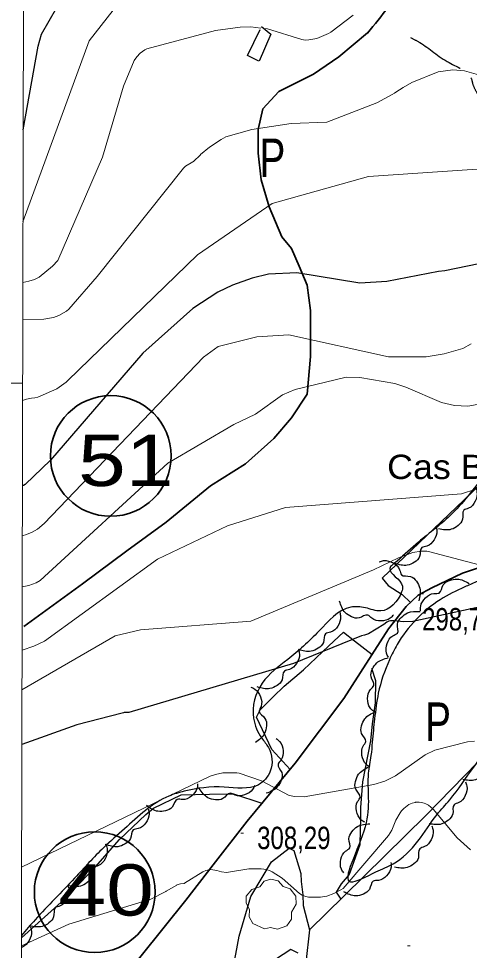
# Model space of a CAD drawing. Extents: x 483847 to 488453, y 4383581 to 4386795.
# Drawn here: x 484103 to 484278.8, y 4385778.6 to 4386142.3 of the extents above; entities that cross this region are included whole.
import ezdxf
from ezdxf.enums import TextEntityAlignment as Align

# ---------------------------------------------------------------- set-up
doc = ezdxf.new("R2010")
doc.units = 0
doc.header["$LTSCALE"] = 3.8
doc.linetypes.add('LONG_DASHED', pattern=[7.5, 6, -1.5])
doc.linetypes.add('MEDIUM_DASHED', pattern=[4.5, 3, -1.5])
for name, color, linetype, lineweight in [('1', 7, 'Continuous', 13), ('13', 7, 'Continuous', 25), ('25', 7, 'LONG_DASHED', 25), ('27', 7, 'Continuous', 25), ('29', 7, 'Continuous', 13), ('38', 7, 'Continuous', 25), ('48', 7, 'MEDIUM_DASHED', 25), ('51', 7, 'Continuous', 13), ('6', 7, 'Continuous', 35), ('7', 7, 'Continuous', 13), ('8', 7, 'Continuous', 25), ('9', 7, 'Continuous', 13)]:
    doc.layers.add(name, color=color, linetype=linetype, lineweight=lineweight)
doc.layers.add('31', color=7, linetype='Continuous')
doc.layers.add('5', color=7, linetype='Continuous')

msp = doc.modelspace()

# ---------------------------------------------------------------- linework, layer by layer
at = {"layer": '1'}
msp.add_line((484104.53, 4386000), (484034.04, 4386000), dxfattribs=at)
msp.add_lwpolyline([(484105.5, 4386448.1), (487681.9, 4386441.2), (487678, 4384129), (484100.5, 4384135.8)], close=True, dxfattribs=at)
at = {"layer": '25'}
for points in [[(484244.76, 4385923.91), (484247.1, 4385921.01), (484252.56, 4385917.53), (484255.79, 4385914.34)], [(484208.88, 4385849.22), (484201.8, 4385856.99), (484195.77, 4385869.63), (484197.2, 4385872.41), (484202.26, 4385877.53), (484206.58, 4385881.72), (484214.07, 4385888.1), (484223.96, 4385897.44), (484229.65, 4385902.75), (484233.96, 4385899.46), (484240.84, 4385894.12)], [(484240.66, 4385888.73), (484242.2, 4385883.98), (484242.03, 4385875.17), (484240.87, 4385866.96), (484240.25, 4385860.34), (484237.08, 4385844.39), (484236.29, 4385834.37), (484236.38, 4385830.12), (484236.25, 4385825.6), (484236.08, 4385819.73), (484231.97, 4385808.21), (484228.85, 4385804.57), (484226.84, 4385801.28), (484228.69, 4385798.57)], [(484104.06, 4385783.51), (484120.82, 4385798.56), (484133.03, 4385811.23), (484142.38, 4385821.8), (484152.55, 4385831.63), (484155.54, 4385834.01), (484166.35, 4385839.3), (484177.48, 4385839.5), (484186.74, 4385839.65), (484197.91, 4385835.98)], [(484186.67, 4385771.46), (484189.03, 4385784.05), (484193.62, 4385799.65), (484198.03, 4385807.02), (484201.67, 4385813.17), (484208.56, 4385818.42), (484210.32, 4385817.49), (484213.12, 4385808.58), (484213.24, 4385805.49), (484213.9, 4385800.29), (484213.92, 4385796.06), (484216.49, 4385786.52), (484214.96, 4385773.81)], [(484212.04, 4385777.4), (484209.19, 4385778.88), (484200.23, 4385773.07)]]:
    msp.add_lwpolyline(points, dxfattribs=at)
at = {"layer": '27'}
for points in [[(484521.83, 4386129.21), (484508.32, 4386113.74), (484496.36, 4386106.72), (484484.98, 4386099.78), (484479.47, 4386096.2), (484474.08, 4386092.03), (484465.73, 4386080.11), (484463.37, 4386070.85), (484462.34, 4386064.2), (484460.12, 4386059.8), (484454.25, 4386057.63), (484450.41, 4386060.19), (484441.8, 4386070.58), (484436.87, 4386074.16), (484423.6, 4386076.36), (484410.55, 4386071.73), (484408.24, 4386063.13), (484410.15, 4386056.7), (484413.78, 4386045.09), (484413.88, 4386035.22), (484411.69, 4386031.3), (484398.49, 4386024.75), (484365.27, 4386031.06), (484366.6, 4386045.65), (484370.89, 4386062.61), (484370.84, 4386067.52), (484358.49, 4386079.04), (484346.94, 4386070.29), (484334.44, 4386055.37), (484325.94, 4386044.05), (484321.89, 4386034.49), (484320.96, 4386033.92), (484314.12, 4386023.53), (484311.47, 4386011.99), (484311.33, 4386008.15), (484312.05, 4385996.07), (484306.71, 4385986.89), (484300.7, 4385979.39), (484285.98, 4385965.15), (484272.14, 4385949.06), (484258.95, 4385937.98), (484250.68, 4385930.52)], [(484281.23, 4385959.28), (484281.77, 4385957.59), (484281.06, 4385953.87), (484278.52, 4385951.18), (484276.64, 4385950.37), (484276.14, 4385946.85), (484274.39, 4385944.43), (484271.76, 4385942.94), (484266.8, 4385943.07)], [(484265.78, 4385944.14), (484266.14, 4385942.4), (484265.02, 4385938.78), (484262.2, 4385936.39), (484260.24, 4385935.79), (484259.36, 4385932.35), (484257.36, 4385930.13), (484254.58, 4385928.95), (484249.66, 4385929.62)], [(484310.59, 4385907.93), (484296.14, 4385903.44), (484289.2, 4385891.6), (484294.68, 4385878.62), (484298.16, 4385870.38), (484294.8, 4385866.22), (484280.49, 4385850.12), (484271.14, 4385837.28), (484266.23, 4385831.62), (484258.71, 4385821.16), (484249.08, 4385812.33), (484242.34, 4385809.17), (484232.5, 4385805.26), (484238.16, 4385826.81), (484239.38, 4385847.7), (484240.42, 4385854.63), (484240.92, 4385859.9), (484241.84, 4385868.97), (484243.29, 4385878.92), (484247.62, 4385892), (484250.65, 4385897.95), (484267.41, 4385915.44), (484276.98, 4385920.43), (484281.49, 4385922.38), (484297.68, 4385928.57), (484310.92, 4385937.54), (484321.22, 4385936.51), (484326.98, 4385931.86), (484335.65, 4385926.29), (484346.17, 4385923.11), (484355.76, 4385923.88), (484349.64, 4385914.35), (484340.44, 4385905.87), (484332.13, 4385896.62), (484324.31, 4385893.84), (484320.63, 4385896.21), (484315.57, 4385899.62), (484312.38, 4385905.09), (484310.59, 4385907.93)], [(484243.66, 4385930.28), (484245.37, 4385930.73), (484249.06, 4385929.82), (484251.6, 4385927.15), (484252.32, 4385925.22), (484255.81, 4385924.54), (484258.13, 4385922.67), (484259.48, 4385919.96), (484259.09, 4385915.02)], [(484250.68, 4385930.52), (484247.76, 4385927.65), (484252.69, 4385920.71), (484252.36, 4385918.5), (484244.24, 4385911.06), (484238.24, 4385912.3), (484232.52, 4385912.53), (484220.11, 4385903.19), (484207.93, 4385892.15), (484198.02, 4385882.9), (484194.6, 4385869.16), (484197.83, 4385861.42), (484200.41, 4385857.74), (484201.16, 4385848.51), (484196.55, 4385843.23), (484183.21, 4385842.3), (484167.6, 4385840.69), (484161.59, 4385838.79), (484144.28, 4385826.05), (484136.18, 4385818.7), (484124.8, 4385806.73), (484109.41, 4385790.47), (484104.06, 4385784.41)], [(484259.8, 4385911.13), (484259.82, 4385912.9), (484261.71, 4385916.2), (484264.97, 4385917.92), (484267.02, 4385918.08), (484268.62, 4385921.25), (484271.06, 4385922.98), (484274.03, 4385923.53), (484278.68, 4385921.81)], [(484249.17, 4385909.48), (484247.92, 4385908.22), (484244.28, 4385907.16), (484240.73, 4385908.19), (484239.15, 4385909.49), (484235.79, 4385908.33), (484232.84, 4385908.78), (484230.32, 4385910.44), (484228.16, 4385914.91)], [(484228.23, 4385910.56), (484228.59, 4385908.82), (484227.48, 4385905.19), (484224.68, 4385902.8), (484222.71, 4385902.19), (484221.85, 4385898.74), (484219.85, 4385896.52), (484217.07, 4385895.33), (484212.15, 4385895.98)], [(484247.2, 4385893), (484246.46, 4385894.61), (484246.73, 4385898.39), (484248.93, 4385901.36), (484250.71, 4385902.39), (484250.78, 4385905.94), (484252.23, 4385908.55), (484254.67, 4385910.34), (484259.61, 4385910.8)], [(484103.97, 4385586.23), (484176.02, 4385651.64), (484253.85, 4385717.49), (484302.32, 4385770.44), (484308.55, 4385772.67), (484311.22, 4385771.78), (484341.46, 4385750.86), (484349.91, 4385746.42), (484353.91, 4385745.08), (484362.36, 4385744.64), (484369.92, 4385748.2), (484474.44, 4385847.42), (484504.68, 4385882.13), (484503.35, 4385888.8), (484498.9, 4385892.81), (484494.45, 4385895.92), (484482, 4385891.47), (484439.31, 4385856.77), (484421.52, 4385849.65), (484402.84, 4385853.65), (484394.83, 4385855.43), (484392.16, 4385853.65), (484393.94, 4385847.42)], [(484212.15, 4385895.98), (484212.52, 4385894.24), (484211.41, 4385890.62), (484208.6, 4385888.22), (484206.64, 4385887.61), (484205.77, 4385884.17), (484203.77, 4385881.95), (484200.99, 4385880.75), (484196.08, 4385881.41)], [(484241.35, 4385871.93), (484240.11, 4385873.21), (484239.12, 4385876.87), (484240.21, 4385880.39), (484241.55, 4385881.95), (484240.44, 4385885.33), (484240.95, 4385888.27), (484242.66, 4385890.76), (484247.17, 4385892.83)], [(484193.51, 4385881.34), (484195.11, 4385880.58), (484197.34, 4385877.51), (484197.56, 4385873.82), (484196.86, 4385871.89), (484199.08, 4385869.12), (484199.64, 4385866.19), (484198.92, 4385863.25), (484195.43, 4385859.73)], [(484239.94, 4385850.17), (484238.51, 4385851.21), (484236.91, 4385854.65), (484237.38, 4385858.31), (484238.44, 4385860.08), (484236.77, 4385863.22), (484236.77, 4385866.2), (484238.03, 4385868.95), (484242.12, 4385871.76)], [(484203.46, 4385861.23), (484204.8, 4385860.07), (484206.13, 4385856.52), (484205.37, 4385852.91), (484204.18, 4385851.23), (484205.59, 4385847.97), (484205.36, 4385844.99), (484203.89, 4385842.35), (484199.59, 4385839.88)], [(484290.5, 4385861.54), (484291.06, 4385859.85), (484290.37, 4385856.12), (484287.85, 4385853.42), (484285.97, 4385852.6), (484285.5, 4385849.07), (484283.77, 4385846.64), (484281.15, 4385845.14), (484276.19, 4385845.23)], [(484237.99, 4385828.57), (484236.53, 4385829.58), (484234.83, 4385832.97), (484235.21, 4385836.64), (484236.21, 4385838.43), (484234.46, 4385841.53), (484234.38, 4385844.51), (484235.56, 4385847.29), (484239.57, 4385850.21)], [(484172.82, 4385843.6), (484172.6, 4385841.84), (484170.37, 4385838.78), (484166.93, 4385837.42), (484164.88, 4385837.49), (484162.93, 4385834.51), (484160.32, 4385833.07), (484157.31, 4385832.84), (484152.87, 4385835.07)], [(484277.26, 4385844.38), (484277.83, 4385842.7), (484277.17, 4385838.97), (484274.68, 4385836.24), (484272.81, 4385835.4), (484272.37, 4385831.87), (484270.66, 4385829.42), (484268.05, 4385827.9), (484263.09, 4385827.95)], [(484195.09, 4385842.96), (484194.27, 4385841.38), (484191.13, 4385839.27), (484187.43, 4385839.17), (484185.53, 4385839.94), (484182.68, 4385837.8), (484179.73, 4385837.34), (484176.82, 4385838.16), (484173.42, 4385841.76)], [(484153.6, 4385833.67), (484153.87, 4385831.92), (484152.58, 4385828.35), (484149.65, 4385826.1), (484147.66, 4385825.6), (484146.62, 4385822.2), (484144.51, 4385820.09), (484141.67, 4385819.04), (484136.8, 4385819.94)], [(484229.8, 4385808.79), (484228.87, 4385810.31), (484228.7, 4385814.1), (484230.53, 4385817.3), (484232.17, 4385818.53), (484231.83, 4385822.07), (484232.96, 4385824.83), (484235.17, 4385826.9), (484240.02, 4385827.94)], [(484264.1, 4385827.14), (484264.63, 4385825.45), (484263.89, 4385821.73), (484261.34, 4385819.06), (484259.45, 4385818.26), (484258.93, 4385814.74), (484257.17, 4385812.33), (484254.53, 4385810.86), (484249.57, 4385811.02)], [(484137.05, 4385819.64), (484137.54, 4385817.93), (484136.71, 4385814.23), (484134.09, 4385811.63), (484132.17, 4385810.88), (484131.57, 4385807.38), (484129.74, 4385805.02), (484127.06, 4385803.62), (484122.11, 4385803.91)], [(484248.22, 4385812.82), (484248.26, 4385811.05), (484246.52, 4385807.68), (484243.32, 4385805.83), (484241.29, 4385805.58), (484239.81, 4385802.35), (484237.45, 4385800.52), (484234.5, 4385799.84), (484229.78, 4385801.37)], [(484122.11, 4385803.9), (484122.61, 4385802.2), (484121.78, 4385798.5), (484119.16, 4385795.89), (484117.25, 4385795.14), (484116.65, 4385791.63), (484114.82, 4385789.27), (484112.15, 4385787.86), (484107.2, 4385788.14)], [(484107.55, 4385787.81), (484108.01, 4385786.1), (484107.11, 4385782.42), (484104.45, 4385779.86), (484104.05, 4385779.71)]]:
    msp.add_spline(points, degree=3, dxfattribs=at)
at = {"layer": '29'}
msp.add_lwpolyline([(484198.92, 4385786.93), (484194.38, 4385789.05), (484192.97, 4385791.59), (484193.07, 4385794.57), (484191.7, 4385796.98), (484191.74, 4385799.73), (484193.9, 4385802.33), (484197.09, 4385803.33), (484198.74, 4385805.52), (484201.31, 4385806.35), (484204.17, 4385805.7), (484206.12, 4385803.43), (484208.93, 4385802.61), (484211.06, 4385799.76), (484211.3, 4385796.63), (484209.42, 4385793.48), (484209.42, 4385790.8), (484207.6, 4385788.19), (484203.98, 4385786.85), (484201.21, 4385787.48)], close=True, dxfattribs=at)
at = {"layer": '38', "linetype": 'LONG_DASHED'}
msp.add_spline([(484255.9, 4386134.9), (484259.44, 4386133.02), (484270.89, 4386125.14), (484279.81, 4386118.06), (484279.96, 4386117.37), (484281.33, 4386114.11), (484286.93, 4386102.77), (484290.45, 4386094.05), (484338.18, 4386033.14), (484340.34, 4386027.35), (484343.3, 4386021.56), (484344.9, 4386017.72), (484345.67, 4386015.54)], degree=3, dxfattribs=at)
at = {"layer": '48'}
msp.add_lwpolyline([(484201.31, 4386136.21), (484196.74, 4386125.7), (484192.21, 4386127.89), (484197.76, 4386139.26)], close=True, dxfattribs=at)
at = {"layer": '51'}
for points in [[(484440.57, 4386075.07), (484408.1, 4386079.76), (484317.55, 4385993.99), (484276.69, 4385954.3), (484244.76, 4385923.91)], [(484317.36, 4385888.26), (484261.85, 4385831.27), (484229.89, 4385799.76), (484216.49, 4385786.52)]]:
    msp.add_lwpolyline(points, dxfattribs=at)
at = {"layer": '6'}
for points in [[(484239.1, 4386136.78), (484227.91, 4386127.44), (484218.03, 4386120.66), (484204.44, 4386113.88), (484198.27, 4386107.09), (484196.42, 4386099.08), (484196.42, 4386089.83), (484197.65, 4386079.35), (484200.74, 4386068.86), (484205.68, 4386057.15), (484209.36, 4386052.55)], [(484209.36, 4386052.55), (484212.47, 4386045.65), (484215.56, 4386038.25), (484216.8, 4386028.37), (484216.8, 4386018.5), (484216.8, 4386010.48), (484215.56, 4385995.67), (484209.38, 4385986.41), (484202.59, 4385978.39), (484191.47, 4385968.52), (484177.89, 4385959.88), (484160.6, 4385945.68), (484145.16, 4385934.58), (484127.86, 4385921.62), (484105.01, 4385904.96)], [(484103.92, 4385718.57), (484111.72, 4385728.95), (484132.39, 4385753.72), (484150.74, 4385776.42), (484168.25, 4385798.21), (484178.85, 4385811.99), (484192.12, 4385829), (484210.84, 4385851.58), (484229.9, 4385876.92), (484247.2, 4385904.12), (484254.19, 4385912.82), (484258.83, 4385917.22), (484264.2, 4385920.12), (484276.08, 4385925.76), (484289.25, 4385930.22), (484301.63, 4385935.61), (484316.4, 4385948.98), (484330.76, 4385961.22)]]:
    msp.add_lwpolyline(points, dxfattribs=at)
for centre in [(484138.92, 4385971.58), (484132.67, 4385801.3)]:
    msp.add_circle(centre, 23.55, dxfattribs=at)
msp.add_spline([(484576.61, 4386447.19), (484575.13, 4386446.53), (484575.18, 4386444.85), (484580.13, 4386440.31), (484591.1, 4386435.01), (484598.73, 4386428.86), (484602.1, 4386423.08), (484602.37, 4386415.22), (484599.42, 4386408.45), (484594.78, 4386406.63), (484585.36, 4386406.05), (484576.72, 4386406.48), (484563.21, 4386405.29), (484545.28, 4386400.82), (484534.96, 4386398.38), (484521.91, 4386395.52), (484514.17, 4386392.31), (484513.85, 4386387.73), (484523.95, 4386384.82), (484528.86, 4386384.69), (484538.58, 4386383.69), (484545.75, 4386380.25), (484548.92, 4386376.43), (484552.06, 4386367.9), (484551.7, 4386358.89), (484550.52, 4386355.02), (484543.31, 4386343.35), (484535.9, 4386336.43), (484527.04, 4386328.4), (484515.84, 4386322.97), (484502.88, 4386315.06), (484490.08, 4386303.77), (484482.61, 4386296.93), (484472.42, 4386287.91), (484462.75, 4386280.64), (484451.72, 4386270.36), (484442.91, 4386255.77), (484439.95, 4386245.25), (484434.08, 4386232.96), (484425.31, 4386219.46), (484419.84, 4386210.8), (484412.03, 4386202.36), (484398.36, 4386194.84), (484387.5, 4386192.19), (484372.49, 4386190.28), (484356.35, 4386188.98), (484338.03, 4386186.55), (484328.45, 4386185.35), (484310.94, 4386184.71), (484289, 4386182.56), (484276.75, 4386181.11), (484267.68, 4386175.87), (484262.62, 4386170.12), (484253.51, 4386158.01), (484247.07, 4386147.03), (484239.03, 4386136.69)], degree=3, dxfattribs=at)
at = {"layer": '7'}
for p, q in [((484259.86, 4385917.82), (484260.86, 4385917.82)), ((484189.64, 4385824.27), (484190.64, 4385824.27)), ((484254.68, 4385780.29), (484255.68, 4385780.29))]:
    msp.add_line(p, q, dxfattribs=at)
at = {"layer": '8'}
for points in [[(484104.74, 4386098.92), (484110.62, 4386131.64), (484111.94, 4386136.21), (484117.94, 4386146.73)], [(484286.93, 4386047.49), (484269.24, 4386043.84), (484266.75, 4386043.6), (484246.61, 4386039.66), (484236.1, 4386039.04), (484211.45, 4386043.13)], [(484211.45, 4386043.13), (484200.41, 4386042.58), (484194.02, 4386040.95), (484186.47, 4386038.25), (484180.65, 4386035.53), (484170.95, 4386029.16), (484151.45, 4386011.69), (484115.42, 4385969.96), (484105.48, 4385960.44), (484104.83, 4385960.08), (484104.44, 4385959.92)], [(484291.44, 4385914.48), (484256.74, 4385906.94), (484253.23, 4385906.88), (484249.31, 4385907.2), (484247.99, 4385907.17), (484247.35, 4385907.03), (484246.87, 4385906.86), (484246.61, 4385906.72), (484245.46, 4385905.84), (484239.48, 4385902.12), (484237.92, 4385901.58), (484236.72, 4385901.38), (484210.16, 4385890.58), (484146.03, 4385871.42), (484144.2, 4385871.39), (484143.86, 4385871.32), (484143.35, 4385871.12), (484125.71, 4385866.64), (484104.23, 4385858.99)]]:
    msp.add_lwpolyline(points, dxfattribs=at)
at = {"layer": '9'}
for points in [[(484104.67, 4386062.98), (484130.5, 4386133.62), (484139.8, 4386145.59)], [(484198.6, 4386138.54), (484200.01, 4386138.38), (484213.42, 4386134.16), (484214.72, 4386133.96), (484216.24, 4386134.03), (484219.24, 4386134.61), (484223.84, 4386136.5), (484224.74, 4386137.01), (484233.49, 4386143.67)], [(484104.62, 4386039.34), (484107.03, 4386039.77), (484109.12, 4386040.45), (484111.06, 4386041.42), (484116.17, 4386045.66), (484118.27, 4386047.94), (484135.76, 4386088.27), (484143.85, 4386115.95), (484148.07, 4386125.93), (484149.06, 4386127.36), (484150.42, 4386128.8), (484152.24, 4386130.16), (484152.93, 4386130.56), (484179.81, 4386137.64), (484189.4, 4386138.98), (484193.58, 4386139.08), (484197.47, 4386138.66)], [(484104.58, 4386024.86), (484112.88, 4386024.98), (484116.57, 4386025.67), (484118.71, 4386026.43), (484121.63, 4386028.09), (484122.6, 4386028.85), (484133.68, 4386041.71), (484167.31, 4386083.95), (484168.08, 4386084.74), (484170.95, 4386086.47), (484171.14, 4386086.61), (484173.87, 4386089.17), (484173.97, 4386089.31), (484177.38, 4386092.2), (484181.96, 4386095.16), (484183.77, 4386096.14), (484193.94, 4386099.09), (484209.24, 4386101.34), (484223.15, 4386101.89), (484242.76, 4386109.43), (484248.73, 4386112.67), (484249.58, 4386113.23), (484250.09, 4386113.67), (484252.97, 4386115.38), (484256.4, 4386117.4), (484266.6, 4386121.61), (484272.32, 4386122.34), (484276.86, 4386121.98), (484286.95, 4386119.1)], [(484297.21, 4386084.65), (484239.52, 4386080.7), (484201.9, 4386070.21), (484172.75, 4386050.14), (484122.18, 4386001.04), (484121.47, 4386000.41), (484117.87, 4385997.82)], [(484279.55, 4386015.33), (484276.29, 4386013.59), (484268.96, 4386011.41), (484261.92, 4386010.24), (484247.31, 4386010.29), (484208.4, 4386018.93), (484195.87, 4386018.07), (484180.87, 4386014.3), (484175.08, 4386010.17), (484113.01, 4385945.26), (484110.36, 4385943.05), (484108.3, 4385941.83), (484106.1, 4385940.9), (484104.4, 4385940.43)], [(484328.87, 4385999.71), (484328.17, 4385999.81), (484324.45, 4385999.71), (484313.15, 4385997.31), (484313.13, 4385997.32), (484278.26, 4385990.97), (484273, 4385991.25), (484267.93, 4385992.47), (484254.03, 4385998.47), (484249.72, 4385999.89), (484236.1, 4386002.26), (484230.73, 4386002.35), (484210.8, 4385997.48), (484205.91, 4385995.44), (484195.38, 4385987.87), (484186.93, 4385983.81), (484161.15, 4385968.83), (484111.43, 4385922.93), (484109.82, 4385922.02), (484106.94, 4385920.96), (484104.36, 4385920.52)], [(484117.87, 4385997.82), (484110.42, 4385994.52), (484109.37, 4385994.28), (484108.03, 4385994.18), (484106.04, 4385993.81), (484104.52, 4385993.29)], [(484286.92, 4385960.41), (484275.67, 4385956.82), (484207.1, 4385951.46), (484184.52, 4385944.25), (484157.13, 4385931.23), (484113.14, 4385899.28), (484108.86, 4385897.26), (484104.31, 4385895.8)], [(484353.21, 4385922.81), (484351.28, 4385922.64), (484349.86, 4385922.77), (484348.75, 4385923.07), (484331.9, 4385932.18), (484329.53, 4385932.91), (484326.19, 4385933.4), (484318.89, 4385933.35), (484317.72, 4385933.15), (484299.01, 4385927.55), (484297.11, 4385927.51), (484282.61, 4385929.1), (484262.84, 4385934.33), (484262.24, 4385934.38), (484259.97, 4385934.36), (484256.79, 4385933.93), (484251.1, 4385931.87), (484241.45, 4385927.14), (484193.61, 4385907.12), (484150.5, 4385903.66), (484140.58, 4385901.41), (484104.27, 4385880.21)], [(484280.76, 4385860.29), (484278.13, 4385860.01), (484265.28, 4385856.7), (484261.53, 4385854.87), (484250.03, 4385846.74), (484245.85, 4385844.66), (484241.52, 4385843.29), (484214.37, 4385838.5), (484210.76, 4385838.58), (484208.48, 4385838.99), (484197.71, 4385844.76), (484188.98, 4385847.77), (484188.13, 4385847.85), (484182.64, 4385847.84), (484179.82, 4385847.25), (484177.76, 4385846.53), (484104.12, 4385811.03)], [(484279.18, 4385817.84), (484273.99, 4385822.54), (484264.73, 4385833.72), (484262.84, 4385835.18), (484261.76, 4385835.78), (484261.13, 4385836.03), (484260.17, 4385836.32), (484259.24, 4385836.47), (484258.03, 4385836.47), (484257.89, 4385836.44), (484257.84, 4385836.4), (484257.82, 4385836.39), (484257.69, 4385836.34), (484256.44, 4385836.09), (484255.15, 4385835.44), (484253.24, 4385833.99), (484252.3, 4385833.02), (484251.78, 4385832.3), (484250.15, 4385829.38), (484248.56, 4385825.53), (484247.28, 4385823.41), (484229.56, 4385802.77), (484228.73, 4385802.2), (484225.89, 4385800.7), (484223.19, 4385799.74), (484223.18, 4385799.74), (484223.16, 4385799.74), (484220.76, 4385799.38), (484216.1, 4385799.35), (484214.98, 4385799.61), (484213.57, 4385800.17), (484212.51, 4385800.77), (484205.77, 4385806.78), (484201.9, 4385809.25), (484201.05, 4385809.65), (484199.61, 4385810.12), (484197.6, 4385810.4), (484192.82, 4385810.37), (484184.03, 4385808.94), (484182.11, 4385809.26), (484180.34, 4385809.76), (484177.98, 4385810.12), (484177.81, 4385810.1), (484176.06, 4385809.74), (484174.84, 4385809.26), (484167.74, 4385804.76), (484167.69, 4385804.73), (484167.68, 4385804.72), (484167.66, 4385804.71), (484167.41, 4385804.71), (484166.08, 4385804.52), (484164.68, 4385804.09), (484164.66, 4385804.07), (484164.64, 4385804.07), (484160.58, 4385801.7), (484160.47, 4385801.59), (484154.6, 4385798.48), (484122.63, 4385788.78), (484104.06, 4385780.33)]]:
    msp.add_lwpolyline(points, dxfattribs=at)

# ---------------------------------------------------------------- texts
at = {"layer": '13', "width": 1.25}
for s, p in [('51', (484144.78, 4385959.85)), ('40', (484137.12, 4385792.15))]:
    msp.add_text(s, height=20, dxfattribs=at).set_placement(p, align=Align.CENTER)
at = {"layer": '31', "width": 0.75}
for p in [(484201.99, 4386080.51), (484266.6, 4385860.34)]:
    msp.add_text('P', height=15, dxfattribs=at).set_placement(p, align=Align.CENTER)
at = {"layer": '5', "width": 1.1}
msp.add_text('Cas Binissalemer', height=9.5, dxfattribs=at).set_placement((484246.72, 4385962.58))
at = {"layer": '7', "width": 0.8}
for s, p in [('298,75', (484260.36, 4385903.45)), ('308,29', (484196.02, 4385818.08))]:
    msp.add_text(s, height=8.75, dxfattribs=at).set_placement(p)

doc.saveas('drawing.dxf')
